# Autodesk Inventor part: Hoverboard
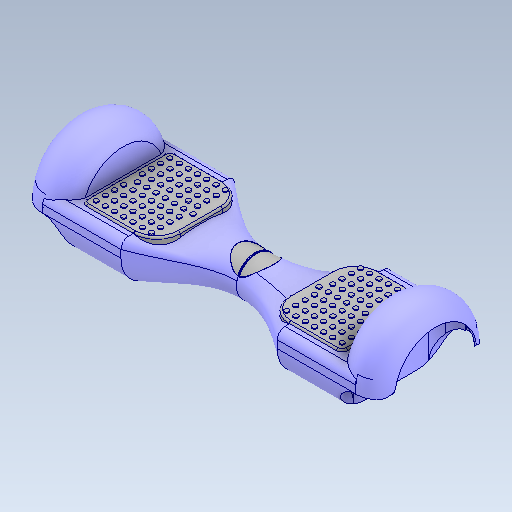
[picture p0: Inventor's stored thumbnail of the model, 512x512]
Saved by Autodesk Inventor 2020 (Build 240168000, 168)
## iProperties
Created: 2020-04
Part Number: Hoverboard
Material: Générique
Document SubType Name: Modeling
Designer: bruno
Density: 1 g/cm^3
Appearance: Par défaut
Mass: 4337.12 g
Surface Area: 3103.23 cm^2
Volume: 4337.12 cm^3
Sending System: SolidWorks 2017
Last Author: hpras
Last Saved: 2020-04-23
Author: bruno
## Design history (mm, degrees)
mirror "Mirror4"
sketch "Esquisse1"
  geometry: L1 (-61.958, 33.92)-(-63.746, -0.188) reference; L2 (-53.301, 36.732)-(-31.808, 10.19) reference; L3 (-49.437, 42.051)-(-17.552, 29.811) reference; L4 (-49.437, 51.153)-(-17.552, 63.393) reference; L5 (-53.301, 56.472)-(-31.808, 83.015) reference; L6 (-61.958, 59.285)-(-63.746, 93.392) reference; L7 (-68.211, 57.253)-(-86.812, 85.897) reference; L8 (-76.179, 50.591)-(-106.551, 58.729) reference; L9 (-76.179, 42.614)-(-106.551, 34.475) reference; L10 (-68.211, 35.951)-(-86.812, 7.307) reference; C1 r 12.7 at (-61.294, 46.602); A1 r 49.95 centre (-61.294, 46.602) between (-85.766, 3.058) and (-67.09, -3.01) reference; A2 r 3 centre (-66.742, -0.031) between (-67.09, -3.01) and (-63.746, -0.188) reference; A3 r 12.7 centre (-61.294, 46.602) between (-61.958, 33.92) and (-53.301, 36.732) reference; A4 r 3 centre (-29.476, 12.078) between (-31.808, 10.19) and (-27.443, 9.872) reference; A5 r 49.95 centre (-61.294, 46.602) between (-27.443, 9.872) and (-15.9, 25.759) reference; A6 r 3 centre (-18.627, 27.01) between (-15.9, 25.759) and (-17.552, 29.811) reference; A7 r 12.7 centre (-61.294, 46.602) between (-49.437, 42.051) and (-49.437, 51.153) reference; A8 r 3 centre (-18.627, 66.194) between (-17.552, 63.393) and (-15.9, 67.446) reference; A9 r 49.95 centre (-61.294, 46.602) between (-15.9, 67.446) and (-27.443, 83.333) reference; A10 r 3 centre (-29.476, 81.127) between (-27.443, 83.333) and (-31.808, 83.015) reference; A11 r 12.7 centre (-61.294, 46.602) between (-53.301, 56.472) and (-61.958, 59.285) reference; A12 r 3 centre (-66.742, 93.235) between (-63.746, 93.392) and (-67.09, 96.215) reference; A13 r 49.95 centre (-61.294, 46.602) between (-67.09, 96.215) and (-85.766, 90.146) reference; A14 r 3 centre (-84.296, 87.531) between (-85.766, 90.146) and (-86.812, 85.897) reference; A15 r 12.7 centre (-61.294, 46.602) between (-68.211, 57.253) and (-72.707, 52.173) reference; A16 r 3 centre (-75.403, 53.489) between (-76.179, 50.591) and (-72.707, 52.173) reference; A17 r 3 centre (-107.328, 55.831) between (-106.551, 58.729) and (-110.269, 56.421) reference; A18 r 49.95 centre (-61.294, 46.602) between (-110.269, 56.421) and (-110.269, 36.784) reference; A19 r 3 centre (-107.328, 37.373) between (-110.269, 36.784) and (-106.551, 34.475) reference; A20 r 3 centre (-75.403, 39.716) between (-72.707, 41.032) and (-76.179, 42.614) reference; A21 r 12.7 centre (-61.294, 46.602) between (-72.707, 41.032) and (-68.211, 35.951) reference; A22 r 3 centre (-84.296, 5.673) between (-86.812, 7.307) and (-85.766, 3.058) reference; 11 further points
  constraints: 1 centre point, 1 coincident
extrude "Extrusion1" cut sketch "Esquisse1" distance "d0" = 10; taper "d1" = 0 deg
sketch "Esquisse2"
  geometry: C1 r 12.7 at (-61.294, 46.602) reference; 1 further point
extrude "Extrusion2" cut sketch "Esquisse2" distance "d2" = 10; taper "d3" = 0 deg
node "Solide1"
node "Référence1"
